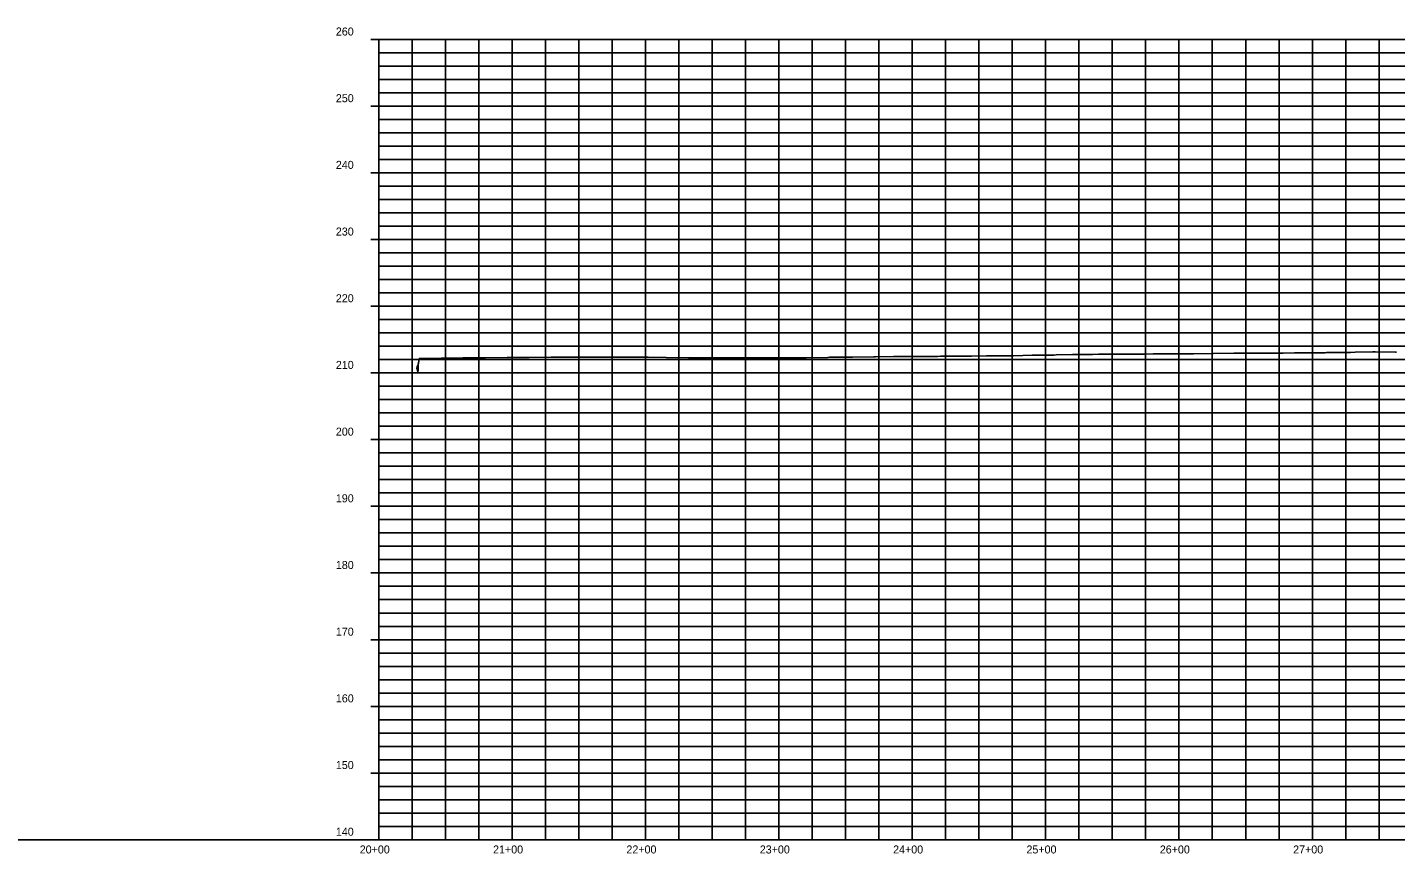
# Model space of a CAD drawing. Extents: x 1732967 to 1742744, y 374025 to 374739.
# Drawn here: x 1733994 to 1735020, y 374119 to 374739 of the extents above; entities that cross this region are included whole.
import ezdxf

# ---------------------------------------------------------------- set-up
doc = ezdxf.new("R2010")
doc.units = 0
for name, color, linetype in [('63', 7, 'Continuous'), ('R_Axis_Annotation', 7, 'Continuous'), ('R_Exist Surface', 7, 'Continuous'), ('R_Grid', 7, 'Continuous'), ('R_Grid Annot', 7, 'Continuous'), ('R_Grid_Minor', 7, 'Continuous')]:
    doc.layers.add(name, color=color, linetype=linetype)

msp = doc.modelspace()

# ---------------------------------------------------------------- linework, layer by layer
msp.add_line((1734257.2, 374129.6), (1732967.4, 374129.6))
at = {"layer": 'R_Exist Surface'}
msp.add_lwpolyline([(1734285.6, 374482.4), (1734285.9, 374484.9), (1734286.4, 374479.5), (1734286.6, 374482.6), (1734286.7, 374486.1), (1734286.8, 374487), (1734287.5, 374490.4), (1734303.8, 374490.7), (1734320.1, 374490.9), (1734320.2, 374490.9), (1734320.2, 374490.9), (1734336.7, 374491), (1734337, 374491), (1734353.3, 374491.1), (1734353.8, 374491.1), (1734369.9, 374491.2), (1734386.3, 374491.4), (1734386.6, 374491.4), (1734403, 374491.3), (1734403.2, 374491.3), (1734419.6, 374491.3), (1734419.8, 374491.3), (1734437.5, 374491.3), (1734437.7, 374491.3), (1734455.5, 374491.4), (1734455.5, 374491.4), (1734455.5, 374491.4), (1734459.1, 374491.3), (1734472.5, 374491.2), (1734472.6, 374491.2), (1734489.4, 374491), (1734489.7, 374491), (1734506.5, 374490.9), (1734506.9, 374490.9), (1734523.5, 374490.8), (1734524.1, 374490.8), (1734541.2, 374490.8), (1734542, 374490.8), (1734559, 374490.8), (1734559.9, 374490.8), (1734576.4, 374491), (1734577.6, 374491), (1734593.8, 374491.2), (1734595.2, 374491.3), (1734611, 374491.5), (1734612.4, 374491.5), (1734628.3, 374491.7), (1734629.5, 374491.7), (1734643.2, 374491.8), (1734644.6, 374491.8), (1734656.2, 374491.9), (1734658.1, 374491.9), (1734660.2, 374491.9), (1734671.3, 374492), (1734676.3, 374492), (1734678.4, 374492.1), (1734686.4, 374492.1), (1734694.5, 374492.2), (1734696.6, 374492.2), (1734701.6, 374492.2), (1734712.8, 374492.3), (1734714.9, 374492.4), (1734716.7, 374492.4), (1734731.1, 374492.5), (1734731.9, 374492.5), (1734733, 374492.5), (1734747, 374492.8), (1734748.1, 374492.8), (1734762.1, 374493), (1734763.4, 374493), (1734765, 374493.1), (1734777.3, 374493.3), (1734780.1, 374493.3), (1734781.4, 374493.3), (1734792.4, 374493.5), (1734796.9, 374493.6), (1734797.8, 374493.6), (1734807.5, 374493.7), (1734814.4, 374493.7), (1734814.9, 374493.7), (1734822.7, 374493.7), (1734832.1, 374493.7), (1734832.1, 374493.7), (1734832.2, 374493.7), (1734837.8, 374493.8), (1734843.5, 374493.8), (1734848.5, 374493.8), (1734848.6, 374493.8), (1734853, 374493.9), (1734865, 374493.9), (1734865.2, 374494), (1734868.1, 374494), (1734882.2, 374494.2), (1734882.7, 374494.2), (1734883.2, 374494.2), (1734898.4, 374494.4), (1734899.4, 374494.4), (1734900.3, 374494.4), (1734913.5, 374494.4), (1734916.8, 374494.5), (1734917.7, 374494.4), (1734928.7, 374494.5), (1734934.2, 374494.5), (1734935.2, 374494.5), (1734943.8, 374494.6), (1734951, 374494.6), (1734958.9, 374494.7), (1734966.7, 374494.7), (1734967.8, 374494.8), (1734974.1, 374494.8), (1734984.6, 374495), (1734985.7, 374495), (1734989.2, 374495.1), (1735002.5, 374495.3), (1735003.6, 374495.3), (1735004.4, 374495.3), (1735019.5, 374495.2), (1735020.3, 374495.2)], dxfattribs=at)
at = {"layer": 'R_Grid'}
for p, q in [((1734257.2, 374129.6), (1734257.2, 374729.6)), ((1734257.2, 374729.6), (1737057.2, 374729.6)), ((1734257.2, 374729.6), (1737057.2, 374729.6)), ((1734357.2, 374129.6), (1734357.2, 374729.6)), ((1734457.2, 374129.6), (1734457.2, 374729.6)), ((1734557.2, 374129.6), (1734557.2, 374729.6)), ((1734657.2, 374129.6), (1734657.2, 374729.6)), ((1734757.2, 374129.6), (1734757.2, 374729.6)), ((1734857.2, 374129.6), (1734857.2, 374729.6)), ((1734957.2, 374129.6), (1734957.2, 374729.6)), ((1734257.2, 374679.6), (1737057.2, 374679.6)), ((1734257.2, 374629.6), (1737057.2, 374629.6)), ((1734257.2, 374579.6), (1737057.2, 374579.6)), ((1734257.2, 374529.6), (1737057.2, 374529.6)), ((1734257.2, 374479.6), (1737057.2, 374479.6)), ((1734257.2, 374429.6), (1737057.2, 374429.6)), ((1734257.2, 374379.6), (1737057.2, 374379.6)), ((1734257.2, 374329.6), (1737057.2, 374329.6)), ((1734257.2, 374279.6), (1737057.2, 374279.6)), ((1734257.2, 374229.6), (1737057.2, 374229.6)), ((1734257.2, 374179.6), (1737057.2, 374179.6)), ((1734257.2, 374129.6), (1737057.2, 374129.6))]:
    msp.add_line(p, q, dxfattribs=at)
at = {"layer": 'R_Grid Annot'}
for p, q in [((1734251.2, 374729.6), (1734257.2, 374729.6)), ((1734251.2, 374729.6), (1734257.2, 374729.6)), ((1734257.2, 374719.6), (1734260.2, 374719.6)), ((1734257.2, 374709.6), (1734260.2, 374709.6)), ((1734257.2, 374699.6), (1734260.2, 374699.6)), ((1734257.2, 374689.6), (1734260.2, 374689.6)), ((1734251.2, 374679.6), (1734257.2, 374679.6)), ((1734257.2, 374669.6), (1734260.2, 374669.6)), ((1734257.2, 374659.6), (1734260.2, 374659.6)), ((1734257.2, 374649.6), (1734260.2, 374649.6)), ((1734257.2, 374639.6), (1734260.2, 374639.6)), ((1734251.2, 374629.6), (1734257.2, 374629.6)), ((1734257.2, 374619.6), (1734260.2, 374619.6)), ((1734257.2, 374609.6), (1734260.2, 374609.6)), ((1734257.2, 374599.6), (1734260.2, 374599.6)), ((1734257.2, 374589.6), (1734260.2, 374589.6)), ((1734251.2, 374579.6), (1734257.2, 374579.6)), ((1734257.2, 374569.6), (1734260.2, 374569.6)), ((1734257.2, 374559.6), (1734260.2, 374559.6)), ((1734257.2, 374549.6), (1734260.2, 374549.6)), ((1734257.2, 374539.6), (1734260.2, 374539.6)), ((1734251.2, 374529.6), (1734257.2, 374529.6)), ((1734257.2, 374519.6), (1734260.2, 374519.6)), ((1734257.2, 374509.6), (1734260.2, 374509.6)), ((1734257.2, 374499.6), (1734260.2, 374499.6)), ((1734257.2, 374489.6), (1734260.2, 374489.6)), ((1734251.2, 374479.6), (1734257.2, 374479.6)), ((1734257.2, 374469.6), (1734260.2, 374469.6)), ((1734257.2, 374459.6), (1734260.2, 374459.6)), ((1734257.2, 374449.6), (1734260.2, 374449.6)), ((1734257.2, 374439.6), (1734260.2, 374439.6)), ((1734251.2, 374429.6), (1734257.2, 374429.6)), ((1734257.2, 374419.6), (1734260.2, 374419.6)), ((1734257.2, 374409.6), (1734260.2, 374409.6)), ((1734257.2, 374399.6), (1734260.2, 374399.6)), ((1734257.2, 374389.6), (1734260.2, 374389.6)), ((1734251.2, 374379.6), (1734257.2, 374379.6)), ((1734257.2, 374369.6), (1734260.2, 374369.6)), ((1734257.2, 374359.6), (1734260.2, 374359.6)), ((1734257.2, 374349.6), (1734260.2, 374349.6)), ((1734257.2, 374339.6), (1734260.2, 374339.6)), ((1734251.2, 374329.6), (1734257.2, 374329.6)), ((1734257.2, 374319.6), (1734260.2, 374319.6)), ((1734257.2, 374309.6), (1734260.2, 374309.6)), ((1734257.2, 374299.6), (1734260.2, 374299.6)), ((1734257.2, 374289.6), (1734260.2, 374289.6)), ((1734251.2, 374279.6), (1734257.2, 374279.6)), ((1734257.2, 374269.6), (1734260.2, 374269.6)), ((1734257.2, 374259.6), (1734260.2, 374259.6)), ((1734257.2, 374249.6), (1734260.2, 374249.6)), ((1734257.2, 374239.6), (1734260.2, 374239.6)), ((1734251.2, 374229.6), (1734257.2, 374229.6)), ((1734257.2, 374219.6), (1734260.2, 374219.6)), ((1734257.2, 374209.6), (1734260.2, 374209.6)), ((1734257.2, 374199.6), (1734260.2, 374199.6)), ((1734257.2, 374189.6), (1734260.2, 374189.6)), ((1734251.2, 374179.6), (1734257.2, 374179.6)), ((1734257.2, 374169.6), (1734260.2, 374169.6)), ((1734257.2, 374159.6), (1734260.2, 374159.6)), ((1734257.2, 374149.6), (1734260.2, 374149.6)), ((1734257.2, 374139.6), (1734260.2, 374139.6)), ((1734251.2, 374129.6), (1734257.2, 374129.6))]:
    msp.add_line(p, q, dxfattribs=at)
at = {"layer": 'R_Grid_Minor'}
for p, q in [((1734282.2, 374129.6), (1734282.2, 374729.6)), ((1734307.2, 374129.6), (1734307.2, 374729.6)), ((1734332.2, 374129.6), (1734332.2, 374729.6)), ((1734382.2, 374129.6), (1734382.2, 374729.6)), ((1734407.2, 374129.6), (1734407.2, 374729.6)), ((1734432.2, 374129.6), (1734432.2, 374729.6)), ((1734482.2, 374129.6), (1734482.2, 374729.6)), ((1734507.2, 374129.6), (1734507.2, 374729.6)), ((1734532.2, 374129.6), (1734532.2, 374729.6)), ((1734582.2, 374129.6), (1734582.2, 374729.6)), ((1734607.2, 374129.6), (1734607.2, 374729.6)), ((1734632.2, 374129.6), (1734632.2, 374729.6)), ((1734682.2, 374129.6), (1734682.2, 374729.6)), ((1734707.2, 374129.6), (1734707.2, 374729.6)), ((1734732.2, 374129.6), (1734732.2, 374729.6)), ((1734782.2, 374129.6), (1734782.2, 374729.6)), ((1734807.2, 374129.6), (1734807.2, 374729.6)), ((1734832.2, 374129.6), (1734832.2, 374729.6)), ((1734882.2, 374129.6), (1734882.2, 374729.6)), ((1734907.2, 374129.6), (1734907.2, 374729.6)), ((1734932.2, 374129.6), (1734932.2, 374729.6)), ((1734982.2, 374129.6), (1734982.2, 374729.6)), ((1735007.2, 374129.6), (1735007.2, 374729.6)), ((1734257.2, 374719.6), (1737057.2, 374719.6)), ((1734257.2, 374709.6), (1737057.2, 374709.6)), ((1734257.2, 374699.6), (1737057.2, 374699.6)), ((1734257.2, 374689.6), (1737057.2, 374689.6)), ((1734257.2, 374669.6), (1737057.2, 374669.6)), ((1734257.2, 374659.6), (1737057.2, 374659.6)), ((1734257.2, 374649.6), (1737057.2, 374649.6)), ((1734257.2, 374639.6), (1737057.2, 374639.6)), ((1734257.2, 374619.6), (1737057.2, 374619.6)), ((1734257.2, 374609.6), (1737057.2, 374609.6)), ((1734257.2, 374599.6), (1737057.2, 374599.6)), ((1734257.2, 374589.6), (1737057.2, 374589.6)), ((1734257.2, 374569.6), (1737057.2, 374569.6)), ((1734257.2, 374559.6), (1737057.2, 374559.6)), ((1734257.2, 374549.6), (1737057.2, 374549.6)), ((1734257.2, 374539.6), (1737057.2, 374539.6)), ((1734257.2, 374519.6), (1737057.2, 374519.6)), ((1734257.2, 374509.6), (1737057.2, 374509.6)), ((1734257.2, 374499.6), (1737057.2, 374499.6)), ((1734257.2, 374489.6), (1737057.2, 374489.6)), ((1734257.2, 374469.6), (1737057.2, 374469.6)), ((1734257.2, 374459.6), (1737057.2, 374459.6)), ((1734257.2, 374449.6), (1737057.2, 374449.6)), ((1734257.2, 374439.6), (1737057.2, 374439.6)), ((1734257.2, 374419.6), (1737057.2, 374419.6)), ((1734257.2, 374409.6), (1737057.2, 374409.6)), ((1734257.2, 374399.6), (1737057.2, 374399.6)), ((1734257.2, 374389.6), (1737057.2, 374389.6)), ((1734257.2, 374369.6), (1737057.2, 374369.6)), ((1734257.2, 374359.6), (1737057.2, 374359.6)), ((1734257.2, 374349.6), (1737057.2, 374349.6)), ((1734257.2, 374339.6), (1737057.2, 374339.6)), ((1734257.2, 374319.6), (1737057.2, 374319.6)), ((1734257.2, 374309.6), (1737057.2, 374309.6)), ((1734257.2, 374299.6), (1737057.2, 374299.6)), ((1734257.2, 374289.6), (1737057.2, 374289.6)), ((1734257.2, 374269.6), (1737057.2, 374269.6)), ((1734257.2, 374259.6), (1737057.2, 374259.6)), ((1734257.2, 374249.6), (1737057.2, 374249.6)), ((1734257.2, 374239.6), (1737057.2, 374239.6)), ((1734257.2, 374219.6), (1737057.2, 374219.6)), ((1734257.2, 374209.6), (1737057.2, 374209.6)), ((1734257.2, 374199.6), (1737057.2, 374199.6)), ((1734257.2, 374189.6), (1737057.2, 374189.6)), ((1734257.2, 374169.6), (1737057.2, 374169.6)), ((1734257.2, 374159.6), (1737057.2, 374159.6)), ((1734257.2, 374149.6), (1737057.2, 374149.6)), ((1734257.2, 374139.6), (1737057.2, 374139.6))]:
    msp.add_line(p, q, dxfattribs=at)

# ---------------------------------------------------------------- texts
at = {"layer": '63'}
msp.add_text('-', height=0.0001, dxfattribs=at).set_placement((1734257.2, 374129.6))
at = {"layer": 'R_Axis_Annotation'}
for s, p in [('260', (1734224.9, 374732.6)), ('260', (1734224.9, 374732.6)), ('250', (1734224.9, 374682.6)), ('240', (1734224.9, 374632.6)), ('230', (1734224.9, 374582.6)), ('220', (1734224.9, 374532.6)), ('210', (1734224.9, 374482.6)), ('200', (1734224.9, 374432.6)), ('190', (1734224.9, 374382.6)), ('180', (1734224.9, 374332.6)), ('170', (1734224.9, 374282.6)), ('160', (1734224.9, 374232.6)), ('150', (1734224.9, 374182.6)), ('140', (1734224.9, 374132.6)), ('20+00', (1734242.8, 374119.3)), ('21+00', (1734342.8, 374119.3)), ('22+00', (1734442.8, 374119.3)), ('23+00', (1734542.8, 374119.3)), ('24+00', (1734642.8, 374119.3)), ('25+00', (1734742.8, 374119.3)), ('26+00', (1734842.8, 374119.3)), ('27+00', (1734942.8, 374119.3))]:
    msp.add_text(s, height=6, dxfattribs=at).set_placement(p)

doc.saveas('drawing.dxf')
